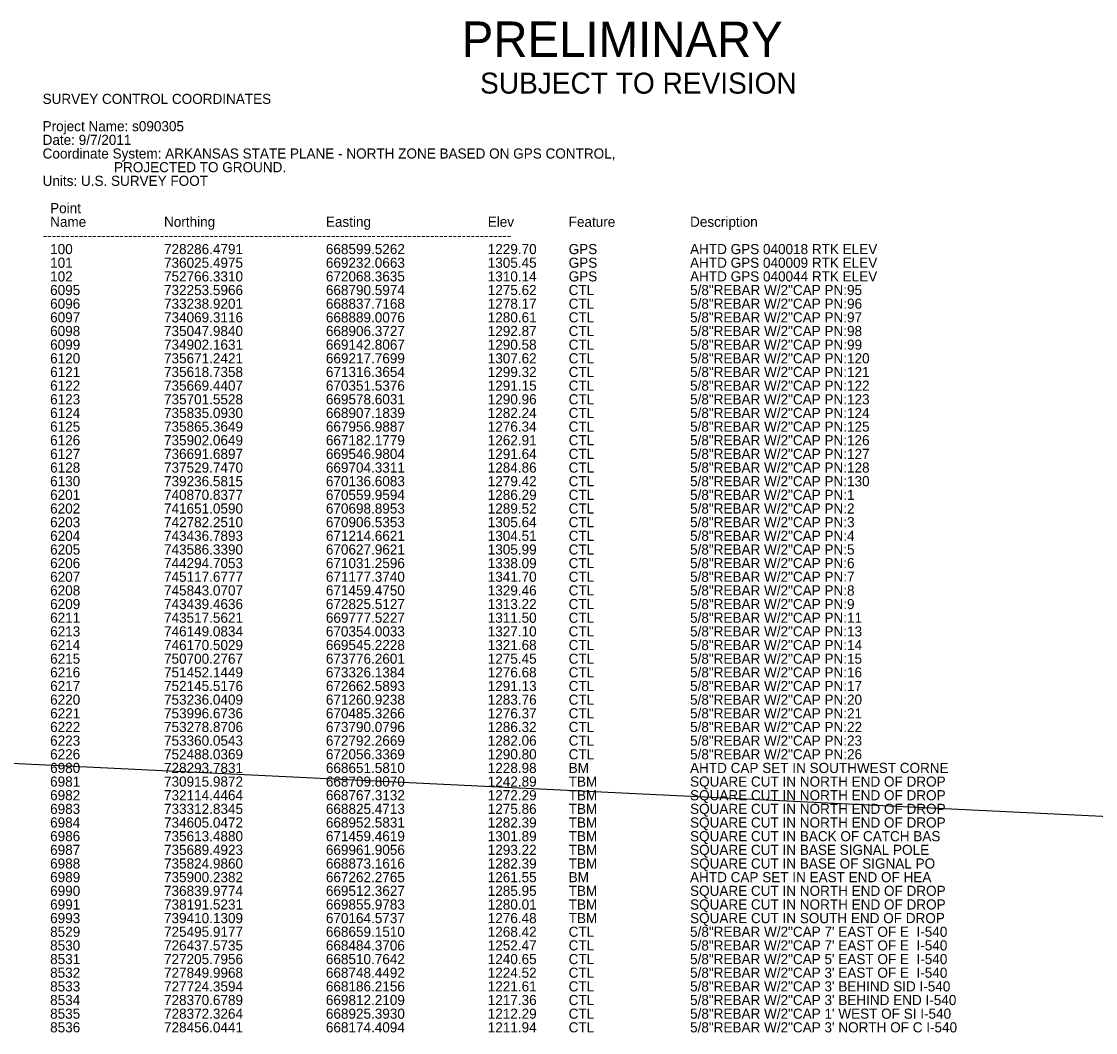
# Model space of a CAD drawing. Extents: x 672566 to 676329, y 739687 to 740710.
# Drawn here: x 673081 to 673612, y 740200 to 740700 of the extents above; entities that cross this region are included whole.
import ezdxf

# ---------------------------------------------------------------- set-up
doc = ezdxf.new("R2010")
doc.units = 0
for name, color, linetype in [('R_Border', 7, 'Continuous'), ('R_Border Prem', 7, 'Continuous'), ('S_BASELINE', 7, 'Continuous')]:
    doc.layers.add(name, color=color, linetype=linetype)

msp = doc.modelspace()

# ---------------------------------------------------------------- linework, layer by layer
at = {"layer": 'R_Border'}
msp.add_lwpolyline([(673921.66, 740294.96), (673903.74, 740292.61), (672625.13, 740354.75)], dxfattribs=at)

# ---------------------------------------------------------------- texts
at = {"layer": 'R_Border Prem'}
for s, height, p in [('PRELIMINARY', 17.5, (673298.96, 740682.18)), ('SUBJECT TO REVISION', 10.3756, (673308, 740664.03))]:
    msp.add_text(s, height=height, rotation=359.9809, dxfattribs=at).set_placement(p)
at = {"layer": 'S_BASELINE'}
for s, p in [('SURVEY CONTROL COORDINATES ', (673091.8, 740658.91)), ('Project Name: s090305 ', (673091.8, 740645.41)), ('Date: 9/7/2011 ', (673091.8, 740638.66)), ('Coordinate System: ARKANSAS STATE PLANE - NORTH ZONE BASED ON GPS CONTROL, ', (673091.8, 740631.91)), ('                   PROJECTED TO GROUND. ', (673091.8, 740625.16)), ('Units: U.S. SURVEY FOOT ', (673091.8, 740618.41)), ('  Point ', (673091.8, 740604.91)), ('  Name     ', (673091.8, 740598.16)), ('Northing', (673151.8, 740598.16)), ('Easting', (673231.8, 740598.16)), ('Elev', (673311.8, 740598.16)), ('Feature', (673351.8, 740598.16)), ('Description ', (673411.8, 740598.16)), ('--------------------------------------------------------------------------------------------------------', (673091.8, 740591.41)), ('  100', (673091.8, 740584.66)), ('728286.4791', (673151.8, 740584.66)), ('668599.5262', (673231.8, 740584.66)), ('1229.70', (673311.8, 740584.66)), ('GPS', (673351.8, 740584.66)), ('AHTD GPS 040018 RTK ELEV ', (673411.8, 740584.66)), ('  101', (673091.8, 740577.91)), ('736025.4975', (673151.8, 740577.91)), ('669232.0663', (673231.8, 740577.91)), ('1305.45', (673311.8, 740577.91)), ('GPS', (673351.8, 740577.91)), ('AHTD GPS 040009 RTK ELEV ', (673411.8, 740577.91)), ('  102', (673091.8, 740571.16)), ('752766.3310', (673151.8, 740571.16)), ('672068.3635', (673231.8, 740571.16)), ('1310.14', (673311.8, 740571.16)), ('GPS', (673351.8, 740571.16)), ('AHTD GPS 040044 RTK ELEV ', (673411.8, 740571.16)), ('  6095', (673091.8, 740564.41)), ('732253.5966', (673151.8, 740564.41)), ('668790.5974', (673231.8, 740564.41)), ('1275.62', (673311.8, 740564.41)), ('CTL', (673351.8, 740564.41)), ('5/8"REBAR W/2"CAP PN:95  ', (673411.8, 740564.41)), ('  6096', (673091.8, 740557.66)), ('733238.9201', (673151.8, 740557.66)), ('668837.7168', (673231.8, 740557.66)), ('1278.17', (673311.8, 740557.66)), ('CTL', (673351.8, 740557.66)), ('5/8"REBAR W/2"CAP PN:96  ', (673411.8, 740557.66)), ('  6097', (673091.8, 740550.91)), ('734069.3116     ', (673151.8, 740550.91)), ('668889.0076 ', (673231.8, 740550.91)), ('1280.61', (673311.8, 740550.91)), ('CTL', (673351.8, 740550.91)), ('5/8"REBAR W/2"CAP PN:97  ', (673411.8, 740550.91)), ('  6098', (673091.8, 740544.16)), ('735047.9840', (673151.8, 740544.16)), ('668906.3727 ', (673231.8, 740544.16)), ('1292.87', (673311.8, 740544.16)), ('CTL', (673351.8, 740544.16)), ('5/8"REBAR W/2"CAP PN:98  ', (673411.8, 740544.16)), ('  6099', (673091.8, 740537.41)), ('734902.1631     ', (673151.8, 740537.41)), ('669142.8067 ', (673231.8, 740537.41)), ('1290.58', (673311.8, 740537.41)), ('CTL', (673351.8, 740537.41)), ('5/8"REBAR W/2"CAP PN:99  ', (673411.8, 740537.41)), ('  6120', (673091.8, 740530.66)), ('735671.2421     ', (673151.8, 740530.66)), ('669217.7699 ', (673231.8, 740530.66)), ('1307.62', (673311.8, 740530.66)), ('CTL', (673351.8, 740530.66)), ('5/8"REBAR W/2"CAP PN:120  ', (673411.8, 740530.66)), ('  6121', (673091.8, 740523.91)), ('735618.7358     ', (673151.8, 740523.91)), ('671316.3654 ', (673231.8, 740523.91)), ('1299.32', (673311.8, 740523.91)), ('CTL', (673351.8, 740523.91)), ('5/8"REBAR W/2"CAP PN:121  ', (673411.8, 740523.91)), ('  6122', (673091.8, 740517.16)), ('735669.4407', (673151.8, 740517.16)), ('670351.5376 ', (673231.8, 740517.16)), ('1291.15', (673311.8, 740517.16)), ('CTL', (673351.8, 740517.16)), ('5/8"REBAR W/2"CAP PN:122  ', (673411.8, 740517.16)), ('  6123', (673091.8, 740510.41)), ('735701.5528     ', (673151.8, 740510.41)), ('669578.6031 ', (673231.8, 740510.41)), ('1290.96', (673311.8, 740510.41)), ('CTL', (673351.8, 740510.41)), ('5/8"REBAR W/2"CAP PN:123  ', (673411.8, 740510.41)), ('  6124', (673091.8, 740503.66)), ('735835.0930', (673151.8, 740503.66)), ('668907.1839 ', (673231.8, 740503.66)), ('1282.24', (673311.8, 740503.66)), ('CTL', (673351.8, 740503.66)), ('5/8"REBAR W/2"CAP PN:124  ', (673411.8, 740503.66)), ('  6125', (673091.8, 740496.91)), ('735865.3649', (673151.8, 740496.91)), ('667956.9887 ', (673231.8, 740496.91)), ('1276.34', (673311.8, 740496.91)), ('CTL', (673351.8, 740496.91)), ('5/8"REBAR W/2"CAP PN:125  ', (673411.8, 740496.91)), ('  6126', (673091.8, 740490.16)), ('735902.0649', (673151.8, 740490.16)), ('667182.1779 ', (673231.8, 740490.16)), ('1262.91', (673311.8, 740490.16)), ('CTL', (673351.8, 740490.16)), ('5/8"REBAR W/2"CAP PN:126 ', (673411.8, 740490.16)), ('  6127', (673091.8, 740483.41)), ('736691.6897     ', (673151.8, 740483.41)), ('669546.9804 ', (673231.8, 740483.41)), ('1291.64', (673311.8, 740483.41)), ('CTL', (673351.8, 740483.41)), ('5/8"REBAR W/2"CAP PN:127  ', (673411.8, 740483.41)), ('  6128', (673091.8, 740476.66)), ('737529.7470', (673151.8, 740476.66)), ('669704.3311 ', (673231.8, 740476.66)), ('1284.86', (673311.8, 740476.66)), ('CTL     ', (673351.8, 740476.66)), ('5/8"REBAR W/2"CAP PN:128  ', (673411.8, 740476.66)), ('  6130', (673091.8, 740469.91)), ('739236.5815     ', (673151.8, 740469.91)), ('670136.6083 ', (673231.8, 740469.91)), ('1279.42', (673311.8, 740469.91)), ('CTL     ', (673351.8, 740469.91)), ('5/8"REBAR W/2"CAP PN:130  ', (673411.8, 740469.91)), ('  6201', (673091.8, 740463.16)), ('740870.8377', (673151.8, 740463.16)), ('670559.9594 ', (673231.8, 740463.16)), ('1286.29', (673311.8, 740463.16)), ('CTL     ', (673351.8, 740463.16)), ('5/8"REBAR W/2"CAP PN:1  ', (673411.8, 740463.16)), ('  6202', (673091.8, 740456.41)), ('741651.0590     ', (673151.8, 740456.41)), ('670698.8953 ', (673231.8, 740456.41)), ('1289.52', (673311.8, 740456.41)), ('CTL     ', (673351.8, 740456.41)), ('5/8"REBAR W/2"CAP PN:2  ', (673411.8, 740456.41)), ('  6203', (673091.8, 740449.66)), ('742782.2510     ', (673151.8, 740449.66)), ('670906.5353 ', (673231.8, 740449.66)), ('1305.64', (673311.8, 740449.66)), ('CTL     ', (673351.8, 740449.66)), ('5/8"REBAR W/2"CAP PN:3  ', (673411.8, 740449.66)), ('  6204', (673091.8, 740442.91)), ('743436.7893', (673151.8, 740442.91)), ('671214.6621 ', (673231.8, 740442.91)), ('1304.51', (673311.8, 740442.91)), ('CTL     ', (673351.8, 740442.91)), ('5/8"REBAR W/2"CAP PN:4  ', (673411.8, 740442.91)), ('  6205', (673091.8, 740436.16)), ('743586.3390', (673151.8, 740436.16)), ('670627.9621 ', (673231.8, 740436.16)), ('1305.99', (673311.8, 740436.16)), ('CTL     ', (673351.8, 740436.16)), ('5/8"REBAR W/2"CAP PN:5  ', (673411.8, 740436.16)), ('  6206', (673091.8, 740429.41)), ('744294.7053', (673151.8, 740429.41)), ('671031.2596 ', (673231.8, 740429.41)), ('1338.09', (673311.8, 740429.41)), ('CTL     ', (673351.8, 740429.41)), ('5/8"REBAR W/2"CAP PN:6  ', (673411.8, 740429.41)), ('  6207', (673091.8, 740422.66)), ('745117.6777     ', (673151.8, 740422.66)), ('671177.3740 ', (673231.8, 740422.66)), ('1341.70', (673311.8, 740422.66)), ('CTL     ', (673351.8, 740422.66)), ('5/8"REBAR W/2"CAP PN:7 ', (673411.8, 740422.66)), ('  6208', (673091.8, 740415.91)), ('745843.0707', (673151.8, 740415.91)), ('671459.4750 ', (673231.8, 740415.91)), ('1329.46', (673311.8, 740415.91)), ('CTL     ', (673351.8, 740415.91)), ('5/8"REBAR W/2"CAP PN:8  ', (673411.8, 740415.91)), ('  6209', (673091.8, 740409.16)), ('743439.4636', (673151.8, 740409.16)), ('672825.5127 ', (673231.8, 740409.16)), ('1313.22', (673311.8, 740409.16)), ('CTL     ', (673351.8, 740409.16)), ('5/8"REBAR W/2"CAP PN:9  ', (673411.8, 740409.16)), ('  6211', (673091.8, 740402.41)), ('743517.5621     ', (673151.8, 740402.41)), ('669777.5227 ', (673231.8, 740402.41)), ('1311.50', (673311.8, 740402.41)), ('CTL     ', (673351.8, 740402.41)), ('5/8"REBAR W/2"CAP PN:11  ', (673411.8, 740402.41)), ('  6213', (673091.8, 740395.66)), ('746149.0834     ', (673151.8, 740395.66)), ('670354.0033 ', (673231.8, 740395.66)), ('1327.10', (673311.8, 740395.66)), ('CTL     ', (673351.8, 740395.66)), ('5/8"REBAR W/2"CAP PN:13  ', (673411.8, 740395.66)), ('  6214', (673091.8, 740388.91)), ('746170.5029     ', (673151.8, 740388.91)), ('669545.2228 ', (673231.8, 740388.91)), ('1321.68', (673311.8, 740388.91)), ('CTL     ', (673351.8, 740388.91)), ('5/8"REBAR W/2"CAP PN:14  ', (673411.8, 740388.91)), ('  6215', (673091.8, 740382.16)), ('750700.2767', (673151.8, 740382.16)), ('673776.2601 ', (673231.8, 740382.16)), ('1275.45', (673311.8, 740382.16)), ('CTL     ', (673351.8, 740382.16)), ('5/8"REBAR W/2"CAP PN:15  ', (673411.8, 740382.16)), ('  6216', (673091.8, 740375.41)), ('751452.1449     ', (673151.8, 740375.41)), ('673326.1384 ', (673231.8, 740375.41)), ('1276.68', (673311.8, 740375.41)), ('CTL     ', (673351.8, 740375.41)), ('5/8"REBAR W/2"CAP PN:16  ', (673411.8, 740375.41)), ('  6217', (673091.8, 740368.66)), ('752145.5176     ', (673151.8, 740368.66)), ('672662.5893', (673231.8, 740368.66)), ('1291.13', (673311.8, 740368.66)), ('CTL     ', (673351.8, 740368.66)), ('5/8"REBAR W/2"CAP PN:17  ', (673411.8, 740368.66)), ('  6220', (673091.8, 740361.91)), ('753236.0409', (673151.8, 740361.91)), ('671260.9238 ', (673231.8, 740361.91)), ('1283.76', (673311.8, 740361.91)), ('CTL     ', (673351.8, 740361.91)), ('5/8"REBAR W/2"CAP PN:20  ', (673411.8, 740361.91)), ('  6221', (673091.8, 740355.16)), ('753996.6736', (673151.8, 740355.16)), ('670485.3266 ', (673231.8, 740355.16)), ('1276.37', (673311.8, 740355.16)), ('CTL     ', (673351.8, 740355.16)), ('5/8"REBAR W/2"CAP PN:21  ', (673411.8, 740355.16)), ('  6222', (673091.8, 740348.41)), ('753278.8706', (673151.8, 740348.41)), ('673790.0796 ', (673231.8, 740348.41)), ('1286.32', (673311.8, 740348.41)), ('CTL     ', (673351.8, 740348.41)), ('5/8"REBAR W/2"CAP PN:22  ', (673411.8, 740348.41)), ('  6223', (673091.8, 740341.66)), ('753360.0543', (673151.8, 740341.66)), ('672792.2669 ', (673231.8, 740341.66)), ('1282.06', (673311.8, 740341.66)), ('CTL     ', (673351.8, 740341.66)), ('5/8"REBAR W/2"CAP PN:23  ', (673411.8, 740341.66)), ('  6226', (673091.8, 740334.91)), ('752488.0369', (673151.8, 740334.91)), ('672056.3369 ', (673231.8, 740334.91)), ('1290.80', (673311.8, 740334.91)), ('CTL     ', (673351.8, 740334.91)), ('5/8"REBAR W/2"CAP PN:26  ', (673411.8, 740334.91)), ('  6980', (673091.8, 740328.16)), ('728293.7831     ', (673151.8, 740328.16)), ('668651.5810 ', (673231.8, 740328.16)), ('1228.98', (673311.8, 740328.16)), ('BM     ', (673351.8, 740328.16)), ('AHTD CAP SET IN SOUTHWEST CORNE ', (673411.8, 740328.16)), ('  6981', (673091.8, 740321.41)), ('730915.9872     ', (673151.8, 740321.41)), ('668709.8070 ', (673231.8, 740321.41)), ('1242.89', (673311.8, 740321.41)), ('TBM     ', (673351.8, 740321.41)), ('SQUARE CUT IN NORTH END OF DROP ', (673411.8, 740321.41)), ('  6982', (673091.8, 740314.66)), ('732114.4464     ', (673151.8, 740314.66)), ('668767.3132 ', (673231.8, 740314.66)), ('1272.29', (673311.8, 740314.66)), ('TBM     ', (673351.8, 740314.66)), ('SQUARE CUT IN NORTH END OF DROP ', (673411.8, 740314.66)), ('  6983', (673091.8, 740307.91)), ('733312.8345     ', (673151.8, 740307.91)), ('668825.4713 ', (673231.8, 740307.91)), ('1275.86', (673311.8, 740307.91)), ('TBM     ', (673351.8, 740307.91)), ('SQUARE CUT IN NORTH END OF DROP ', (673411.8, 740307.91)), ('  6984', (673091.8, 740301.16)), ('734605.0472', (673151.8, 740301.16)), ('668952.5831 ', (673231.8, 740301.16)), ('1282.39', (673311.8, 740301.16)), ('TBM     ', (673351.8, 740301.16)), ('SQUARE CUT IN NORTH END OF DROP ', (673411.8, 740301.16)), ('  6986', (673091.8, 740294.41)), ('735613.4880     ', (673151.8, 740294.41)), ('671459.4619 ', (673231.8, 740294.41)), ('1301.89', (673311.8, 740294.41)), ('TBM     ', (673351.8, 740294.41)), ('SQUARE CUT IN BACK OF CATCH BAS ', (673411.8, 740294.41)), ('  6987', (673091.8, 740287.66)), ('735689.4923', (673151.8, 740287.66)), ('669961.9056 ', (673231.8, 740287.66)), ('1293.22', (673311.8, 740287.66)), ('TBM     ', (673351.8, 740287.66)), ('SQUARE CUT IN BASE SIGNAL POLE  ', (673411.8, 740287.66)), ('  6988', (673091.8, 740280.91)), ('735824.9860', (673151.8, 740280.91)), ('668873.1616 ', (673231.8, 740280.91)), ('1282.39', (673311.8, 740280.91)), ('TBM     ', (673351.8, 740280.91)), ('SQUARE CUT IN BASE OF SIGNAL PO ', (673411.8, 740280.91)), ('  6989', (673091.8, 740274.16)), ('735900.2382', (673151.8, 740274.16)), ('667262.2765 ', (673231.8, 740274.16)), ('1261.55', (673311.8, 740274.16)), ('BM     ', (673351.8, 740274.16)), ('AHTD CAP SET IN EAST END OF HEA ', (673411.8, 740274.16)), ('  6990', (673091.8, 740267.41)), ('736839.9774', (673151.8, 740267.41)), ('669512.3627 ', (673231.8, 740267.41)), ('1285.95', (673311.8, 740267.41)), ('TBM     ', (673351.8, 740267.41)), ('SQUARE CUT IN NORTH END OF DROP ', (673411.8, 740267.41)), ('  6991', (673091.8, 740260.66)), ('738191.5231     ', (673151.8, 740260.66)), ('669855.9783 ', (673231.8, 740260.66)), ('1280.01', (673311.8, 740260.66)), ('TBM     ', (673351.8, 740260.66)), ('SQUARE CUT IN NORTH END OF DROP ', (673411.8, 740260.66)), ('  6993', (673091.8, 740253.91)), ('739410.1309     ', (673151.8, 740253.91)), ('670164.5737 ', (673231.8, 740253.91)), ('1276.48', (673311.8, 740253.91)), ('TBM     ', (673351.8, 740253.91)), ('SQUARE CUT IN SOUTH END OF DROP ', (673411.8, 740253.91)), ('  8529', (673091.8, 740247.16)), ('725495.9177', (673151.8, 740247.16)), ('668659.1510 ', (673231.8, 740247.16)), ('1268.42', (673311.8, 740247.16)), ('CTL     ', (673351.8, 740247.16)), ('5/8"REBAR W/2"CAP 7\' EAST OF E  I-540 ', (673411.8, 740247.16)), ('  8530', (673091.8, 740240.41)), ('726437.5735', (673151.8, 740240.41)), ('668484.3706 ', (673231.8, 740240.41)), ('1252.47', (673311.8, 740240.41)), ('CTL     ', (673351.8, 740240.41)), ('5/8"REBAR W/2"CAP 7\' EAST OF E  I-540 ', (673411.8, 740240.41)), ('  8531', (673091.8, 740233.66)), ('727205.7956', (673151.8, 740233.66)), ('668510.7642 ', (673231.8, 740233.66)), ('1240.65', (673311.8, 740233.66)), ('CTL     ', (673351.8, 740233.66)), ('5/8"REBAR W/2"CAP 5\' EAST OF E  I-540 ', (673411.8, 740233.66)), ('  8532', (673091.8, 740226.91)), ('727849.9968', (673151.8, 740226.91)), ('668748.4492 ', (673231.8, 740226.91)), ('1224.52', (673311.8, 740226.91)), ('CTL     ', (673351.8, 740226.91)), ('5/8"REBAR W/2"CAP 3\' EAST OF E  I-540 ', (673411.8, 740226.91)), ('  8533', (673091.8, 740220.16)), ('727724.3594', (673151.8, 740220.16)), ('668186.2156 ', (673231.8, 740220.16)), ('1221.61', (673311.8, 740220.16)), ('CTL     ', (673351.8, 740220.16)), ('5/8"REBAR W/2"CAP 3\' BEHIND SID I-540 ', (673411.8, 740220.16)), ('  8534', (673091.8, 740213.41)), ('728370.6789', (673151.8, 740213.41)), ('669812.2109 ', (673231.8, 740213.41)), ('1217.36', (673311.8, 740213.41)), ('CTL     ', (673351.8, 740213.41)), ('5/8"REBAR W/2"CAP 3\' BEHIND END I-540 ', (673411.8, 740213.41)), ('  8535', (673091.8, 740206.66)), ('728372.3264', (673151.8, 740206.66)), ('668925.3930 ', (673231.8, 740206.66)), ('1212.29', (673311.8, 740206.66)), ('CTL     ', (673351.8, 740206.66)), ('5/8"REBAR W/2"CAP 1\' WEST OF SI I-540 ', (673411.8, 740206.66)), ('  8536', (673091.8, 740199.91)), ('728456.0441     ', (673151.8, 740199.91)), ('668174.4094 ', (673231.8, 740199.91)), ('1211.94', (673311.8, 740199.91)), ('CTL     ', (673351.8, 740199.91)), ('5/8"REBAR W/2"CAP 3\' NORTH OF C I-540 ', (673411.8, 740199.91))]:
    msp.add_text(s, height=5, dxfattribs=at).set_placement(p)

doc.saveas('drawing.dxf')
